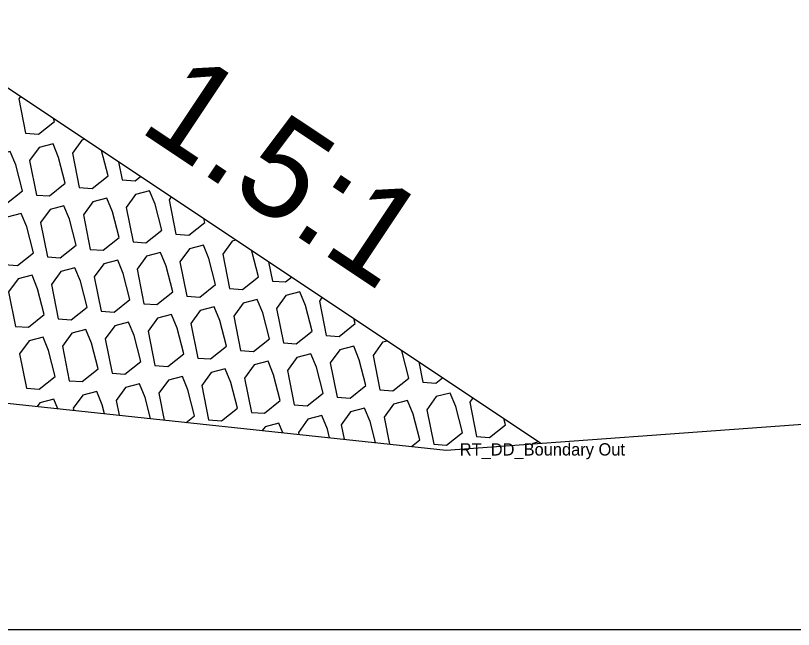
# Model space of a CAD drawing. Extents: x -26 to 203, y -10 to 20020.
# Drawn here: x 133.55 to 139.89, y 2500 to 2505 of the extents above; entities that cross this region are included whole.
import ezdxf

# ---------------------------------------------------------------- set-up
doc = ezdxf.new("R2010")
doc.units = 0
for name, color, linetype in [('Default', 7, 'Continuous'), ('Exist Cross Section Cell', 7, 'Continuous'), ('Exist XS Ground Line', 7, 'Continuous'), ('Old_Level_1', 7, 'Continuous'), ('Prop CMT Rip Rap Class II', 7, 'Continuous'), ('Prop XS Side Slope Text', 7, 'Continuous')]:
    doc.layers.add(name, color=color, linetype=linetype)

msp = doc.modelspace()

# ---------------------------------------------------------------- linework, layer by layer
at = {"layer": 'Exist Cross Section Cell'}
msp.add_line((100, 2500), (200, 2500), dxfattribs=at)
at = {"layer": 'Exist XS Ground Line'}
for p, q in [((137.0597, 2501.4604), (149.0311, 2502.331)), ((132.0245, 2501.998), (137.0597, 2501.4604))]:
    msp.add_line(p, q, dxfattribs=at)
at = {"layer": 'Old_Level_1'}
for p, q in [((134.3929, 2503.809), (134.4222, 2503.6613)), ((135.6146, 2502.9945), (135.6458, 2502.8375)), ((136.8363, 2502.1799), (136.8693, 2502.0138)), ((137.6551, 2501.6341), (137.6554, 2501.6327)), ((137.6554, 2501.6327), (137.6574, 2501.6325))]:
    msp.add_line(p, q, dxfattribs=at)
for points in [[(133.5943, 2504.3414), (133.5805, 2504.3224), (133.6361, 2504.0424)], [(133.6361, 2504.0424), (133.7414, 2504.0348), (133.8709, 2504.138), (133.865, 2504.1609)], [(134.1181, 2503.9922), (134.0951, 2503.9862), (134.018, 2503.8798), (134.0736, 2503.5998)], [(134.0736, 2503.5998), (134.1789, 2503.5922), (134.3084, 2503.6954), (134.2553, 2503.9007)], [(134.4222, 2503.6613), (134.5275, 2503.6536), (134.5723, 2503.6894)], [(134.8217, 2503.5231), (134.8041, 2503.4987), (134.8597, 2503.2187)], [(134.8597, 2503.2187), (134.965, 2503.211), (135.0945, 2503.3142), (135.0861, 2503.3468)], [(135.3503, 2503.1707), (135.3186, 2503.1625), (135.2416, 2503.0561), (135.2972, 2502.7761)], [(135.2972, 2502.7761), (135.4024, 2502.7684), (135.532, 2502.8716), (135.4775, 2503.0822), (135.4755, 2503.0872)], [(135.6458, 2502.8375), (135.751, 2502.8299), (135.8013, 2502.87)], [(136.0492, 2502.7047), (136.0276, 2502.6749), (136.0832, 2502.3949)], [(136.0832, 2502.3949), (136.1885, 2502.3873), (136.318, 2502.4905), (136.3071, 2502.5328)], [(136.5825, 2502.3492), (136.5422, 2502.3388), (136.4651, 2502.2323), (136.5207, 2501.9523)], [(136.5207, 2501.9523), (136.626, 2501.9447), (136.7555, 2502.0479), (136.7011, 2502.2585), (136.6945, 2502.2745)], [(134.9443, 2501.6862), (135.0125, 2501.7406), (134.9581, 2501.9511), (134.9129, 2502.0608), (134.7992, 2502.0314), (134.7221, 2501.925), (134.7658, 2501.7053)], [(136.8693, 2502.0138), (136.9746, 2502.0062), (137.0303, 2502.0506)], [(134.6541, 2501.7172), (134.6095, 2501.8897), (134.5643, 2501.9994), (134.4506, 2501.97), (134.3735, 2501.8635), (134.3971, 2501.7447)], [(134.2792, 2501.7572), (134.2609, 2501.8282), (134.2158, 2501.9379), (134.102, 2501.9085), (134.0249, 2501.8021), (134.0285, 2501.784)], [(133.8995, 2501.7978), (133.8672, 2501.8764), (133.7534, 2501.847), (133.7308, 2501.8158)], [(136.7775, 2501.4905), (136.8444, 2501.5438), (136.79, 2501.7544), (136.7448, 2501.8641), (136.6311, 2501.8347), (136.554, 2501.7283), (136.5974, 2501.5097)], [(137.2767, 2501.8864), (137.2512, 2501.8512), (137.3068, 2501.5712)], [(136.4856, 2501.5217), (136.4414, 2501.6929), (136.3962, 2501.8026), (136.2825, 2501.7732), (136.2054, 2501.6668), (136.2288, 2501.5491)], [(136.1108, 2501.5617), (136.0928, 2501.6315), (136.0476, 2501.7412), (135.9339, 2501.7118), (135.8568, 2501.6053), (135.8601, 2501.5884)], [(137.3068, 2501.5712), (137.4121, 2501.5636), (137.5416, 2501.6668), (137.5282, 2501.7187)], [(135.7309, 2501.6022), (135.699, 2501.6797), (135.5853, 2501.6503), (135.5634, 2501.6201)], [(137.8147, 2501.5277), (137.7657, 2501.515), (137.7632, 2501.5115)]]:
    msp.add_lwpolyline(points, dxfattribs=at)
for points in [[(133.725, 2503.5383), (133.8303, 2503.5307), (133.9598, 2503.6339), (133.9054, 2503.8445), (133.8602, 2503.9542), (133.7465, 2503.9248), (133.6694, 2503.8183)], [(133.3764, 2503.4769), (133.4817, 2503.4692), (133.6112, 2503.5724), (133.5568, 2503.783), (133.5116, 2503.8927), (133.3979, 2503.8633), (133.3208, 2503.7569)], [(134.5111, 2503.1572), (134.6164, 2503.1496), (134.7459, 2503.2528), (134.6914, 2503.4634), (134.6463, 2503.573), (134.5325, 2503.5436), (134.4555, 2503.4372)], [(134.1625, 2503.0957), (134.2678, 2503.0881), (134.3973, 2503.1913), (134.3429, 2503.4019), (134.2977, 2503.5116), (134.1839, 2503.4822), (134.1069, 2503.3757)], [(133.8139, 2503.0343), (133.9192, 2503.0266), (134.0487, 2503.1298), (133.9943, 2503.3404), (133.9491, 2503.4501), (133.8354, 2503.4207), (133.7583, 2503.3143)], [(133.4653, 2502.9728), (133.5706, 2502.9652), (133.7001, 2503.0684), (133.6457, 2503.2789), (133.6005, 2503.3886), (133.4868, 2503.3592), (133.4097, 2503.2528)], [(134.9486, 2502.7146), (135.0538, 2502.707), (135.1834, 2502.8102), (135.1289, 2503.0207), (135.0838, 2503.1304), (134.97, 2503.101), (134.893, 2502.9946)], [(134.6, 2502.6531), (134.7052, 2502.6455), (134.8348, 2502.7487), (134.7803, 2502.9593), (134.7352, 2503.069), (134.6214, 2503.0396), (134.5444, 2502.9331)], [(134.2514, 2502.5917), (134.3566, 2502.584), (134.4862, 2502.6872), (134.4317, 2502.8978), (134.3866, 2503.0075), (134.2728, 2502.9781), (134.1958, 2502.8717)], [(133.9028, 2502.5302), (134.008, 2502.5226), (134.1376, 2502.6258), (134.0831, 2502.8363), (134.038, 2502.946), (133.9242, 2502.9166), (133.8472, 2502.8102)], [(133.5542, 2502.4687), (133.6594, 2502.4611), (133.789, 2502.5643), (133.7345, 2502.7749), (133.6894, 2502.8846), (133.5756, 2502.8552), (133.4986, 2502.7487)], [(135.7346, 2502.3335), (135.8399, 2502.3258), (135.9694, 2502.429), (135.915, 2502.6396), (135.8699, 2502.7493), (135.7561, 2502.7199), (135.679, 2502.6135)], [(135.386, 2502.272), (135.4913, 2502.2644), (135.6208, 2502.3676), (135.5664, 2502.5781), (135.5213, 2502.6878), (135.4075, 2502.6584), (135.3304, 2502.552)], [(135.0374, 2502.2105), (135.1427, 2502.2029), (135.2723, 2502.3061), (135.2178, 2502.5167), (135.1727, 2502.6264), (135.0589, 2502.597), (134.9818, 2502.4905)], [(134.6889, 2502.1491), (134.7941, 2502.1414), (134.9237, 2502.2446), (134.8692, 2502.4552), (134.8241, 2502.5649), (134.7103, 2502.5355), (134.6332, 2502.4291)], [(134.3403, 2502.0876), (134.4455, 2502.08), (134.5751, 2502.1832), (134.5206, 2502.3937), (134.4755, 2502.5034), (134.3617, 2502.474), (134.2846, 2502.3676)], [(133.9917, 2502.0261), (134.0969, 2502.0185), (134.2265, 2502.1217), (134.172, 2502.3323), (134.1269, 2502.442), (134.0131, 2502.4126), (133.9361, 2502.3061)], [(133.6431, 2501.9647), (133.7483, 2501.957), (133.8779, 2502.0602), (133.8234, 2502.2708), (133.7783, 2502.3805), (133.6645, 2502.3511), (133.5875, 2502.2447)], [(136.1721, 2501.8909), (136.2774, 2501.8832), (136.4069, 2501.9864), (136.3525, 2502.197), (136.3073, 2502.3067), (136.1936, 2502.2773), (136.1165, 2502.1709)], [(135.8235, 2501.8294), (135.9288, 2501.8218), (136.0583, 2501.925), (136.0039, 2502.1355), (135.9587, 2502.2452), (135.845, 2502.2158), (135.7679, 2502.1094)], [(135.4749, 2501.7679), (135.5802, 2501.7603), (135.7097, 2501.8635), (135.6553, 2502.0741), (135.6101, 2502.1838), (135.4964, 2502.1544), (135.4193, 2502.0479)], [(135.1263, 2501.7065), (135.2316, 2501.6988), (135.3611, 2501.802), (135.3067, 2502.0126), (135.2615, 2502.1223), (135.1478, 2502.0929), (135.0707, 2501.9865)], [(136.9582, 2501.5097), (137.0635, 2501.5021), (137.193, 2501.6053), (137.1386, 2501.8159), (137.0934, 2501.9256), (136.9796, 2501.8962), (136.9026, 2501.7897)]]:
    msp.add_lwpolyline(points, close=True, dxfattribs=at)
at = {"layer": 'Prop CMT Rip Rap Class II'}
msp.add_lwpolyline([(119.8779, 2505), (132.6064, 2505), (137.8315, 2501.5165)], dxfattribs=at)

# ---------------------------------------------------------------- texts
at = {"layer": 'Default'}
msp.add_text('RT_DD_Boundary Out', height=0.1, dxfattribs=at).set_placement((137.1702, 2501.4165))
at = {"layer": 'Prop XS Side Slope Text'}
msp.add_text('1.5:1', height=0.8, rotation=326.30861, dxfattribs=at).set_placement((134.5426, 2504.0697))

doc.saveas('drawing.dxf')
